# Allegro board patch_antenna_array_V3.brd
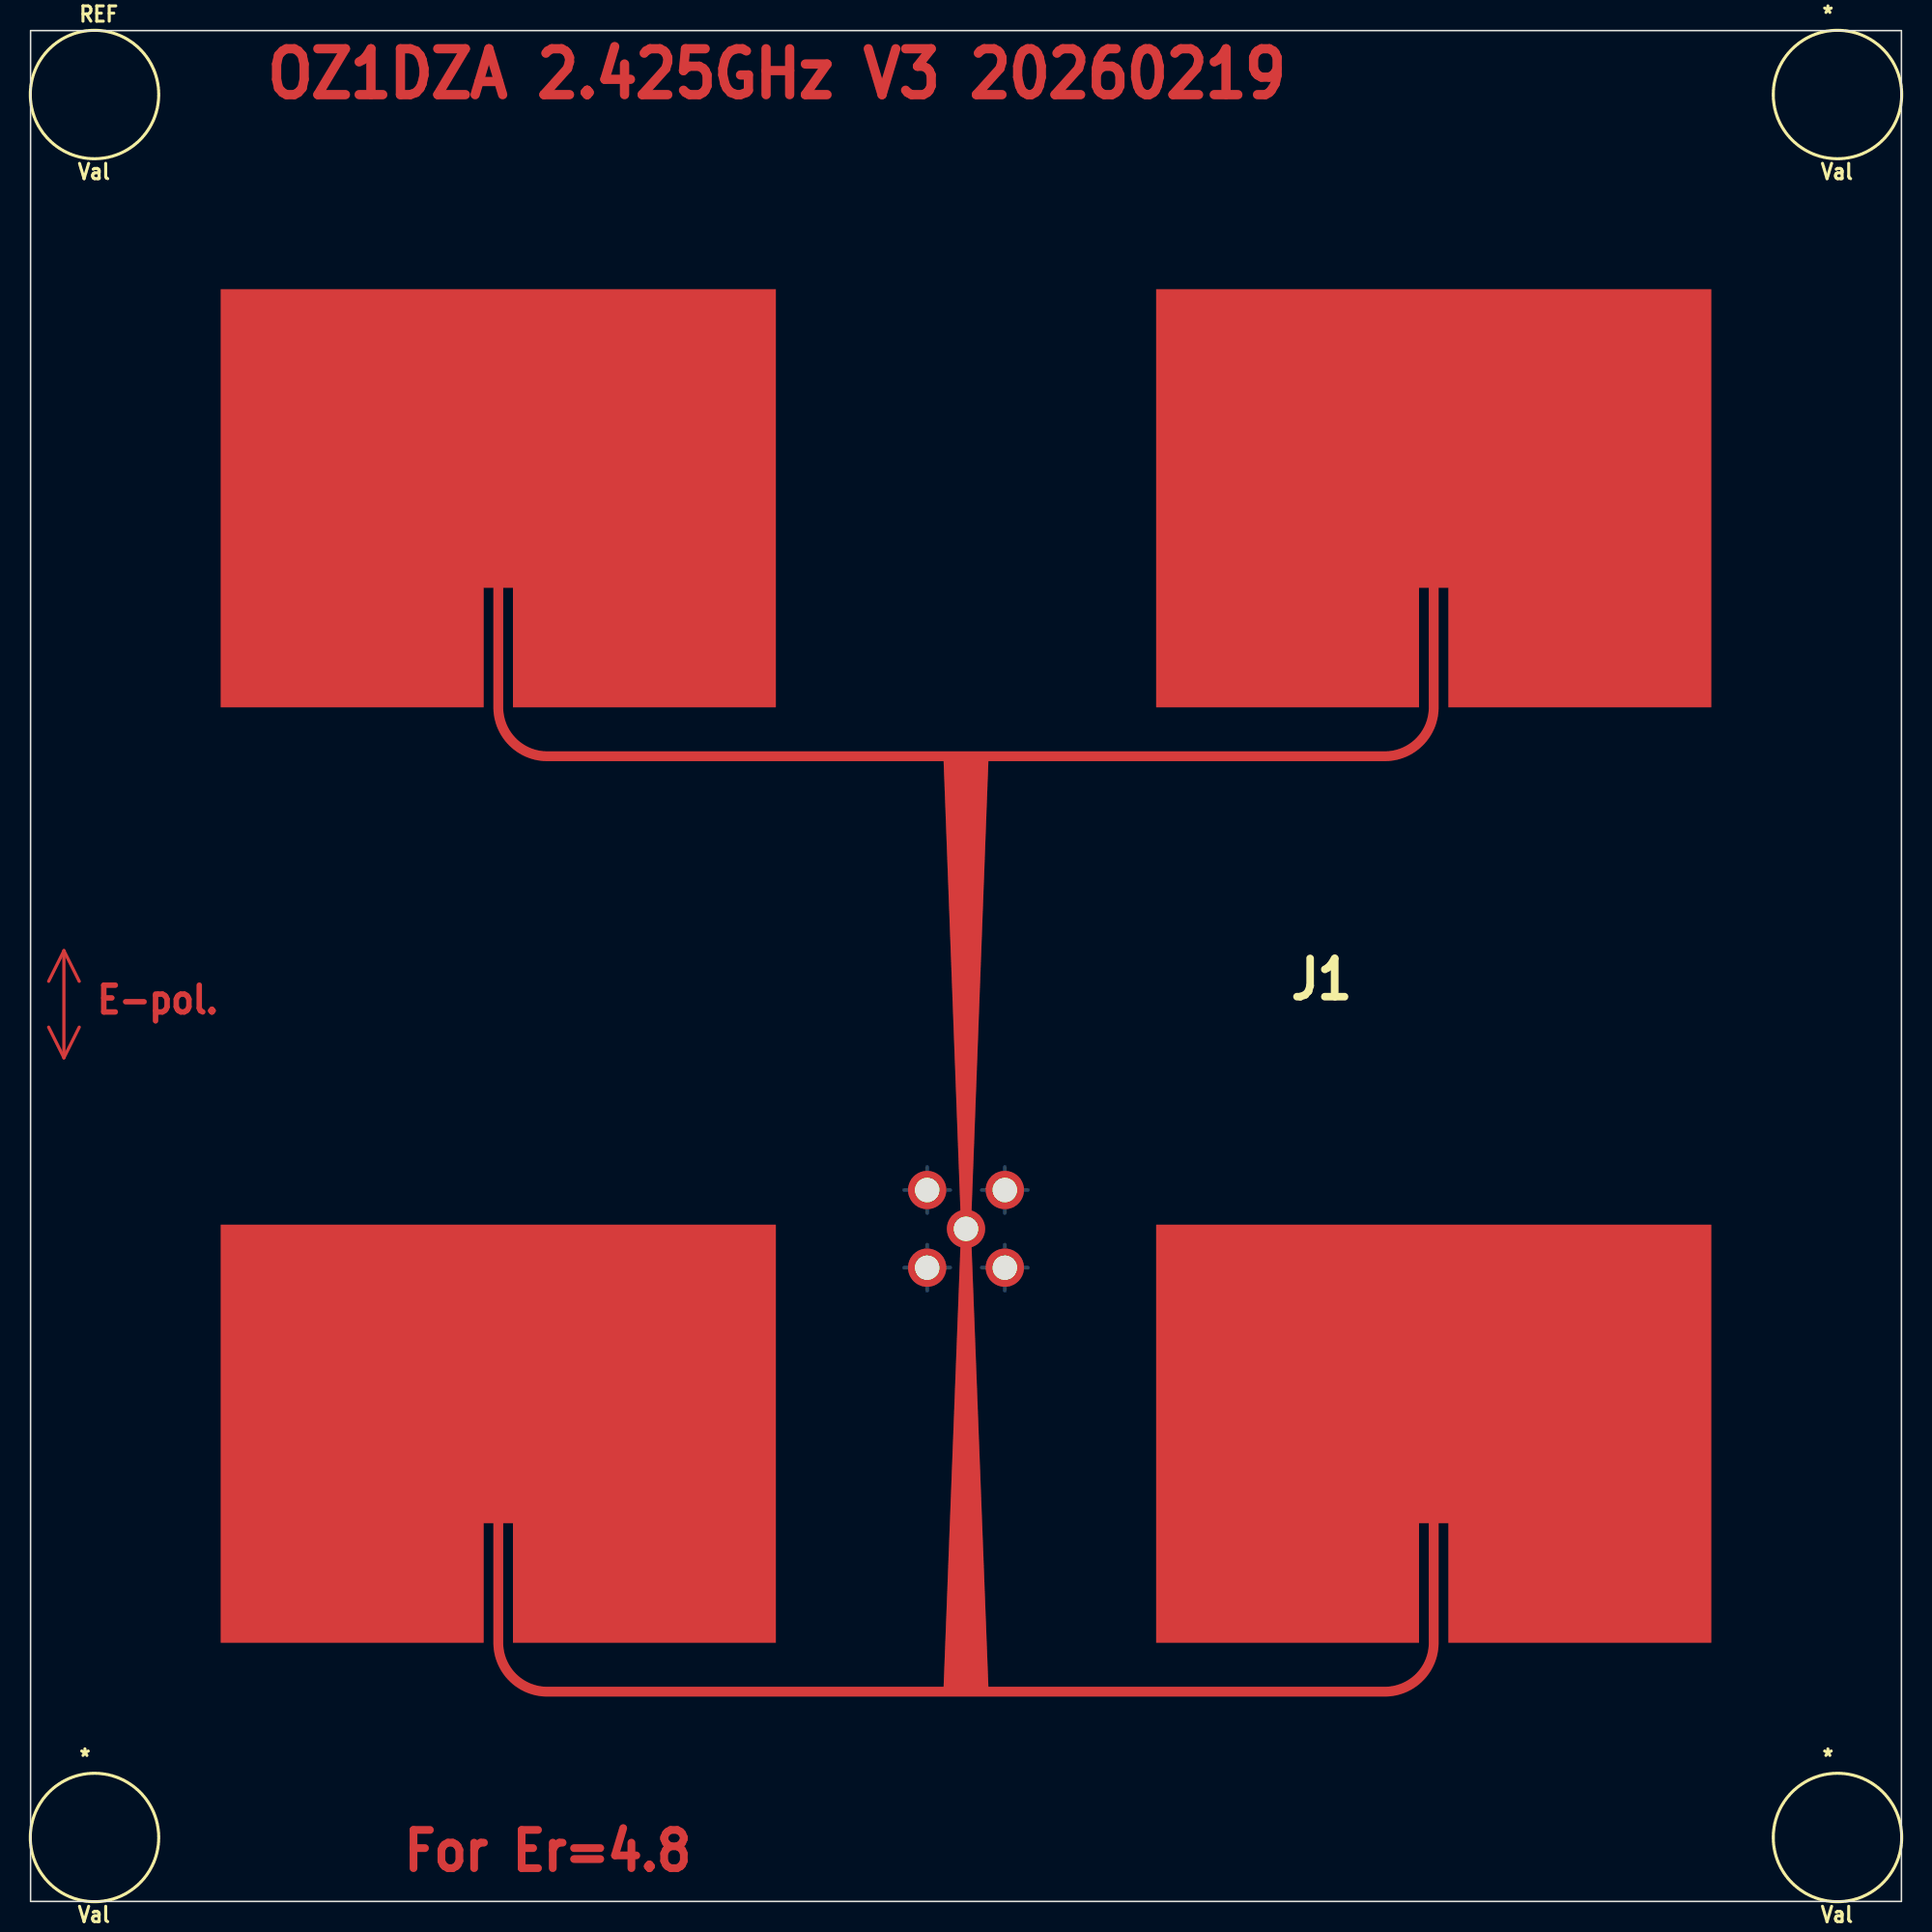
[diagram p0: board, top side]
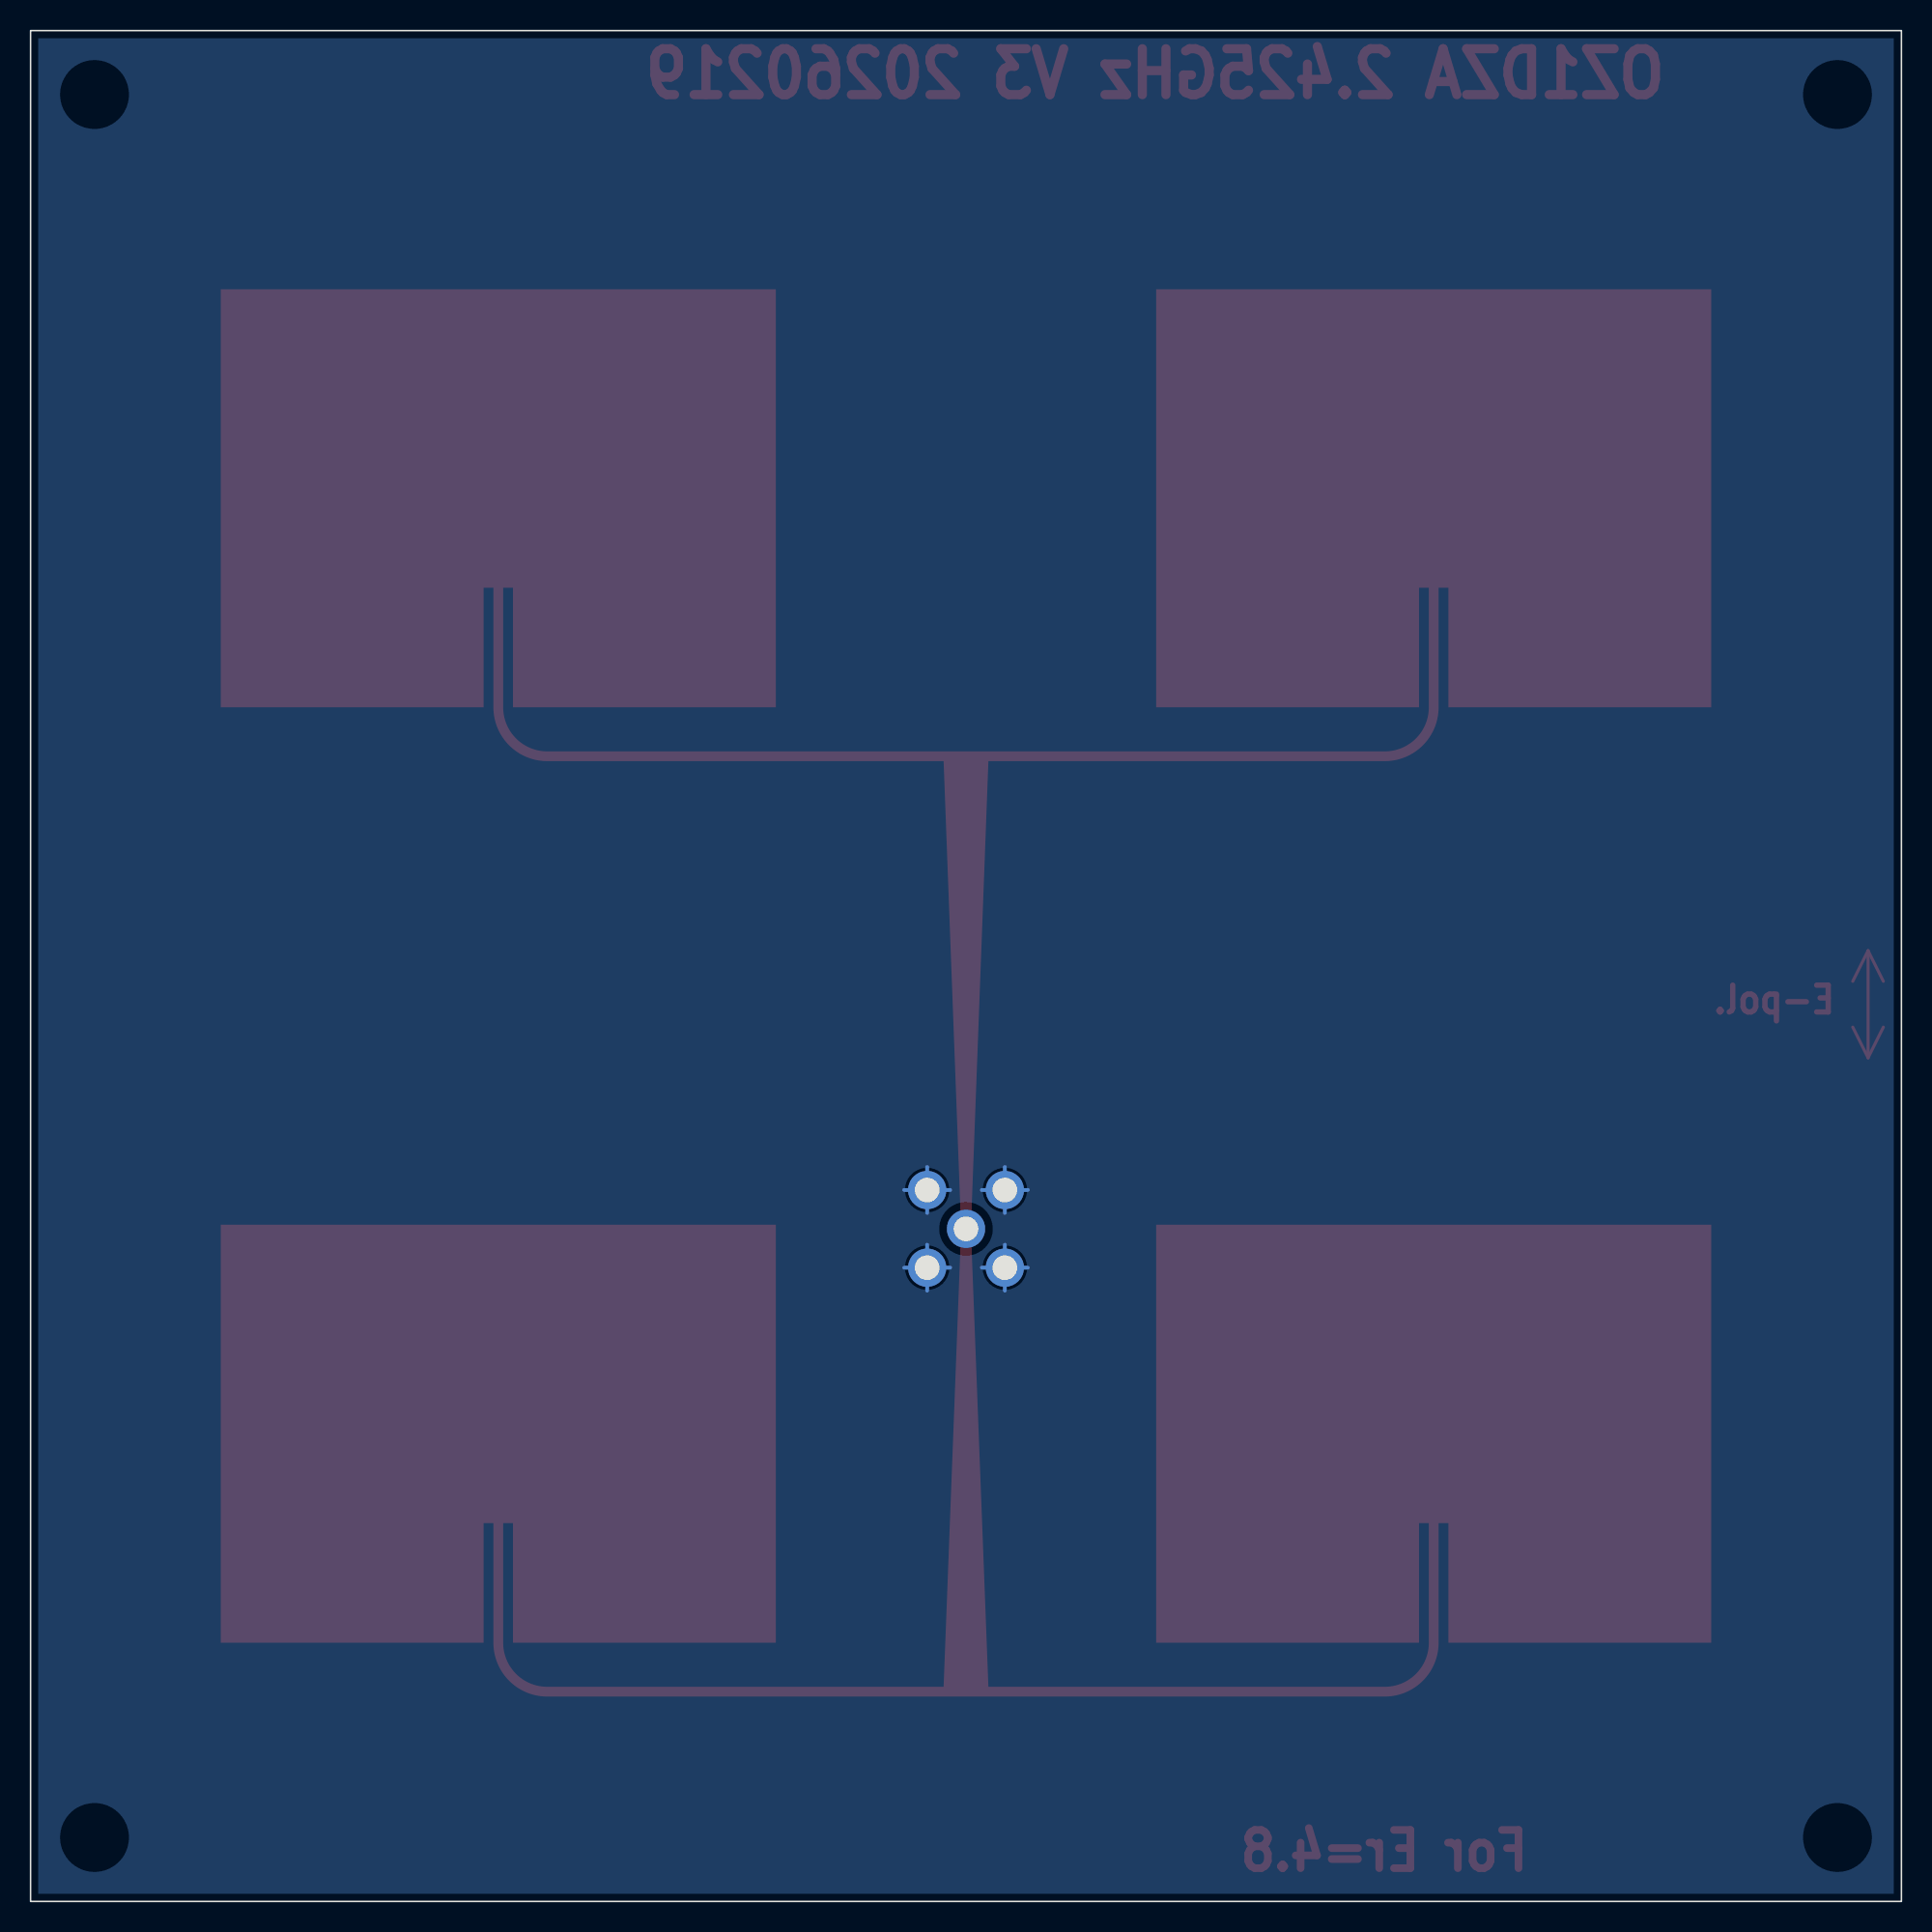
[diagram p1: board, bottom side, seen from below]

Outline 122.36 x 122.36 mm; copper layers: TOP, BOTTOM. Coordinates in mm from the lower left corner of the outline.
Outline path: rectangle 0,0 122.36,122.36

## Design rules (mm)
constraint set DEFAULT: min track width 0.3

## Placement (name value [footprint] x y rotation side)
J1  patch_antenna_array  [PATCH_ANTENNA_ARRAY]  61.18 61.18 0 top
NOREF  -  []  0 0 0 top
NOREF#2  -  []  122.36 0 90 top
REF  Val  [unnamed#2]  4.18 118.18 0 top
UNK*  Val  [unnamed#2]  118.18 4.18 0 top
UNK*#2  Val  [unnamed#2]  118.18 118.18 0 top
UNK*#3  Val  [unnamed#2]  4.18 4.18 0 top

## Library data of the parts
J1 = CON5

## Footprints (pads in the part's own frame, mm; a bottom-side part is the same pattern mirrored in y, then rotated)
PATCH_ANTENNA_ARRAY
  round 2.5 hole 1.6: 1(0,-17.192) 2(2.54,-14.652) 3(-2.54,-14.652) 4(-2.54,-19.732) 5(2.54,-19.732)
unnamed#2
  round 0 hole 3.5 unplated: (0,0)

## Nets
GND: J1.2 J1.3 J1.4 J1.5

Pads without a net: J1 1

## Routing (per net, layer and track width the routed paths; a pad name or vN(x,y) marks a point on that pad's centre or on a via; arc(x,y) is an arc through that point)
GND: length 24
  BOTTOM w0.25: J1.4 60.14,41.45 ; J1.4 58.64,39.95 ; J1.4 58.64,42.95 ; J1.4 57.14,41.45 ; J1.3 60.14,46.53 ; J1.3 58.64,48.03 ; J1.3 57.14,46.53 ; J1.3 58.64,45.03 ; 63.72,39.95 J1.5 ; J1.5 65.22,41.45 ; J1.5 62.22,41.45 ; J1.5 63.72,42.95 ; J1.2 63.72,48.03 ; J1.2 63.72,45.03 ; J1.2 65.22,46.53 ; J1.2 62.22,46.53

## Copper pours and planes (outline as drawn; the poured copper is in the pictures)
GND on BOTTOM: 0,122.36 0,0 122.36,0 122.36,122.36
Net_7 on TOP (solid shape): 48.74,78.1 31.55,78.1 31.55,85.93 30.91,85.93 30.91,78.1 31.75,76.06 33.79,75.22 88.57,75.22 90.61,76.06 91.45,78.1 91.45,85.93 90.81,85.93 90.81,78.1 73.62,78.1 73.62,105.44 109.93,105.44 109.93,78.1 92.73,78.1 92.73,85.93 92.09,85.93 92.09,78.1 91.06,75.61 88.57,74.58 62.65,74.58 61.51,44.31 62.14,44.31 62.14,43.67 61.51,43.67 62.65,14.04 88.57,14.04 90.61,14.88 91.45,16.92 91.45,24.74 90.81,24.74 90.81,16.92 73.62,16.92 73.62,44.26 109.93,44.26 109.93,16.92 92.73,16.92 92.73,24.74 92.09,24.74 92.09,16.92 91.06,14.43 88.57,13.4 33.79,13.4 31.3,14.43 30.27,16.92 30.27,24.74 29.63,24.74 29.63,16.92 12.44,16.92 12.44,44.26 48.74,44.26 48.74,16.92 31.55,16.92 31.55,24.74 30.91,24.74 30.91,16.92 31.75,14.88 33.79,14.04 59.72,14.04 60.86,43.99 59.72,74.58 33.79,74.58 31.3,75.61 30.27,78.1 30.27,85.93 29.63,85.93 29.63,78.1 12.44,78.1 12.44,105.44 48.74,105.44

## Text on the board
TOP: E-pol. | For Er=4.8 | OZ1DZA 2.425GHz V3 20260219
